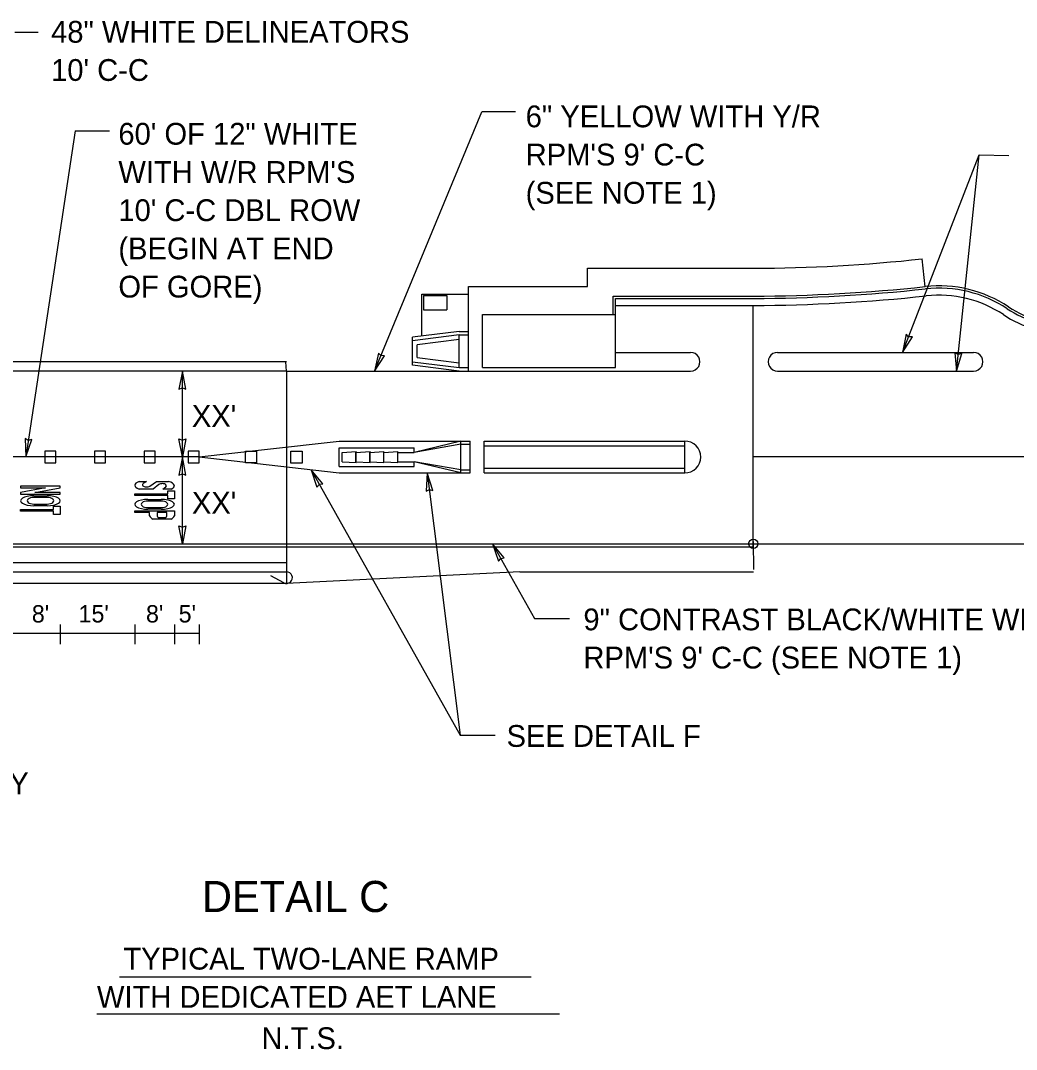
# Model space of a CAD drawing. Extents: x 583689 to 590775, y 1496016 to 1497365.
# Drawn here: x 587578.1 to 587898.1, y 1496113.3 to 1496443.8 of the extents above; entities that cross this region are included whole.
import ezdxf

# ---------------------------------------------------------------- set-up
doc = ezdxf.new("R2010")
doc.units = 0
for name, color, linetype in [('2', 7, 'Continuous'), ('21', 7, 'Continuous'), ('22', 7, 'Continuous'), ('28', 7, 'Continuous'), ('3', 7, 'Continuous'), ('41', 7, 'Continuous'), ('42', 7, 'Continuous'), ('46', 7, 'Continuous'), ('50', 7, 'Continuous'), ('52', 7, 'Continuous'), ('PavtMessage', 7, 'Continuous'), ('TextLabel', 7, 'Continuous')]:
    doc.layers.add(name, color=color, linetype=linetype)

msp = doc.modelspace()

# ---------------------------------------------------------------- linework, layer by layer
at = {"layer": '2'}
for p, q in [((587760.33, 1496364.3), (587813.57, 1496364.31)), ((587760.33, 1496358.37), (587760.33, 1496364.3)), ((587868.77, 1496358.35), (587867.8, 1496367.29)), ((587722.07, 1496349.37), (587722.07, 1496358.37)), ((587722.07, 1496358.37), (587760.33, 1496358.37)), ((587707.07, 1496355.99), (587722.07, 1496356)), ((587707.08, 1496342.5), (587707.07, 1496355.99)), ((587768.57, 1496355.31), (587813.56, 1496355.31)), ((587768.57, 1496349.38), (587768.57, 1496355.3)), ((587769.32, 1496332.37), (587769.32, 1496354.56)), ((587769.32, 1496354.56), (587813.56, 1496354.56)), ((587769.32, 1496352.31), (587813.57, 1496352.31)), ((587813.57, 1496275.75), (587813.57, 1496352.31)), ((587722.07, 1496331.25), (587722.07, 1496349.37)), ((587726.57, 1496349.37), (587769.32, 1496349.38)), ((587726.57, 1496332.38), (587726.57, 1496349.37)), ((587719.07, 1496344), (587704.07, 1496342.13)), ((587719.07, 1496342.87), (587704.07, 1496340.99)), ((587704.07, 1496333.13), (587704.07, 1496342.13)), ((587719.07, 1496341.35), (587705.57, 1496339.67)), ((587719.07, 1496344), (587722.07, 1496344)), ((587719.07, 1496332.38), (587719.07, 1496342.88)), ((587719.07, 1496342.88), (587722.07, 1496342.88)), ((587705.57, 1496335.58), (587705.57, 1496339.67)), ((587705.57, 1496335.58), (587719.07, 1496333.9)), ((587769.32, 1496337.25), (587793.42, 1496337.25)), ((587663.57, 1496331.25), (587326.15, 1496331.25)), ((587663.57, 1496331.25), (587793.42, 1496331.25)), ((587663.58, 1496331.25), (587663.58, 1496275.75)), ((587704.07, 1496334.26), (587719.07, 1496332.38)), ((587719.07, 1496331.25), (587704.07, 1496333.13)), ((587719.07, 1496332.38), (587722.07, 1496332.39)), ((587726.57, 1496332.38), (587769.32, 1496332.37)), ((587656.54, 1496306.03), (587680.53, 1496308.76)), ((587680.53, 1496308.73), (587722.57, 1496308.75)), ((587719.57, 1496308.75), (587704.57, 1496305.13)), ((587719.57, 1496298.5), (587719.57, 1496308.75)), ((587722.57, 1496298.5), (587722.57, 1496308.75)), ((587727.07, 1496298.5), (587727.07, 1496308.75)), ((587727.07, 1496308.75), (587791.54, 1496308.75)), ((587791.54, 1496298.5), (587791.54, 1496308.75)), ((587635.53, 1496303.64), (587656.54, 1496306.03)), ((587680.53, 1496306.63), (587704.57, 1496306.63)), ((587680.53, 1496300.63), (587680.53, 1496306.63)), ((587681.44, 1496305.12), (587685.94, 1496305.37)), ((587681.44, 1496305.12), (587685.94, 1496305.37)), ((587681.44, 1496305.12), (587685.94, 1496305.37)), ((587681.44, 1496305.12), (587685.94, 1496305.37)), ((587681.44, 1496302.12), (587681.44, 1496305.13)), ((587681.44, 1496302.12), (587681.44, 1496305.13)), ((587681.44, 1496302.12), (587681.44, 1496305.13)), ((587681.44, 1496302.12), (587681.44, 1496305.13)), ((587681.44, 1496302.11), (587681.44, 1496305.13)), ((587681.44, 1496302.11), (587681.44, 1496305.13)), ((587681.44, 1496302.11), (587681.44, 1496305.13)), ((587681.44, 1496302.11), (587681.44, 1496305.13)), ((587681.44, 1496302.11), (587681.44, 1496305.13)), ((587681.44, 1496302.11), (587681.44, 1496305.13)), ((587681.44, 1496302.11), (587681.44, 1496305.13)), ((587681.44, 1496302.11), (587681.44, 1496305.13)), ((587681.44, 1496302.1), (587681.44, 1496305.12)), ((587681.44, 1496302.1), (587681.44, 1496305.12)), ((587681.44, 1496302.1), (587681.44, 1496305.12)), ((587681.44, 1496302.1), (587681.44, 1496305.12)), ((587685.9, 1496305.12), (587690.4, 1496305.38)), ((587685.9, 1496305.12), (587690.4, 1496305.38)), ((587685.9, 1496305.12), (587690.4, 1496305.38)), ((587685.9, 1496305.12), (587690.4, 1496305.38)), ((587685.9, 1496302.11), (587685.9, 1496305.12)), ((587685.9, 1496302.11), (587685.9, 1496305.12)), ((587685.9, 1496302.11), (587685.9, 1496305.12)), ((587685.9, 1496302.11), (587685.9, 1496305.12)), ((587685.91, 1496302.1), (587685.9, 1496305.12)), ((587685.91, 1496302.1), (587685.9, 1496305.12)), ((587685.91, 1496302.1), (587685.9, 1496305.12)), ((587685.91, 1496302.1), (587685.9, 1496305.12)), ((587685.91, 1496302.1), (587685.9, 1496305.12)), ((587685.91, 1496302.1), (587685.9, 1496305.12)), ((587685.91, 1496302.1), (587685.9, 1496305.12)), ((587685.91, 1496302.1), (587685.9, 1496305.12)), ((587685.94, 1496301.87), (587685.94, 1496305.37)), ((587685.94, 1496301.87), (587685.94, 1496305.37)), ((587685.94, 1496301.87), (587685.94, 1496305.37)), ((587685.94, 1496301.87), (587685.94, 1496305.37)), ((587690.36, 1496305.13), (587694.86, 1496305.38)), ((587690.36, 1496305.13), (587694.86, 1496305.38)), ((587690.36, 1496302.11), (587690.36, 1496305.13)), ((587690.36, 1496302.11), (587690.36, 1496305.13)), ((587690.36, 1496302.11), (587690.36, 1496305.13)), ((587690.36, 1496302.11), (587690.36, 1496305.13)), ((587690.36, 1496302.11), (587690.36, 1496305.13)), ((587690.36, 1496302.11), (587690.36, 1496305.13)), ((587690.36, 1496302.11), (587690.36, 1496305.13)), ((587690.36, 1496302.11), (587690.36, 1496305.13)), ((587690.4, 1496301.88), (587690.4, 1496305.38)), ((587690.4, 1496301.88), (587690.4, 1496305.38)), ((587690.4, 1496301.88), (587690.4, 1496305.38)), ((587690.4, 1496301.88), (587690.4, 1496305.38)), ((587694.82, 1496305.13), (587699.32, 1496305.38)), ((587694.82, 1496302.11), (587694.82, 1496305.13)), ((587694.82, 1496302.11), (587694.82, 1496305.13)), ((587694.86, 1496301.88), (587694.86, 1496305.38)), ((587694.86, 1496301.88), (587694.86, 1496305.38)), ((587699.32, 1496301.88), (587699.32, 1496305.38)), ((587699.32, 1496305.13), (587704.57, 1496305.13)), ((587719.57, 1496307.76), (587704.57, 1496305.13)), ((587704.57, 1496305.13), (587704.57, 1496306.63)), ((587719.57, 1496307.76), (587722.55, 1496307.76)), ((587727.07, 1496307.25), (587762.14, 1496307.25)), ((587762.14, 1496307.25), (587791.54, 1496307.25)), ((587635.53, 1496303.64), (587539.85, 1496303.64)), ((587635.53, 1496303.64), (587653.24, 1496301.62)), ((587653.24, 1496301.62), (587680.53, 1496298.5)), ((587681.44, 1496302.1), (587685.94, 1496301.87)), ((587681.44, 1496302.1), (587685.94, 1496301.87)), ((587681.44, 1496302.1), (587685.94, 1496301.87)), ((587681.44, 1496302.1), (587685.94, 1496301.87)), ((587685.9, 1496302.11), (587690.4, 1496301.88)), ((587685.9, 1496302.11), (587690.4, 1496301.88)), ((587685.9, 1496302.11), (587690.4, 1496301.88)), ((587685.9, 1496302.11), (587690.4, 1496301.88)), ((587690.36, 1496302.11), (587694.86, 1496301.88)), ((587690.36, 1496302.11), (587694.86, 1496301.88)), ((587694.82, 1496302.11), (587699.32, 1496301.88)), ((587699.32, 1496302.13), (587704.57, 1496302.13)), ((587704.57, 1496300.63), (587704.57, 1496302.19)), ((587719.57, 1496298.5), (587704.57, 1496302.13)), ((587719.57, 1496299.5), (587704.57, 1496302.13)), ((587813.57, 1496303.79), (588039.9, 1496303.8)), ((587680.53, 1496300.63), (587704.57, 1496300.63)), ((587680.53, 1496298.52), (587722.57, 1496298.5)), ((587719.57, 1496299.5), (587722.58, 1496299.5)), ((587727.07, 1496300), (587762.46, 1496300)), ((587727.07, 1496298.5), (587791.54, 1496298.5)), ((587762.46, 1496300), (587791.54, 1496300)), ((587387.69, 1496275.75), (587663.57, 1496275.75)), ((587663.57, 1496275.75), (587774.7, 1496275.75)), ((587663.57, 1496275.75), (588039.9, 1496275.75)), ((587774.7, 1496275.75), (587813.57, 1496275.76)), ((587813.57, 1496274.75), (587813.57, 1496275.75)), ((587813.57, 1496274.75), (587813.57, 1496275.75)), ((587326.15, 1496274.75), (587663.58, 1496274.75)), ((587663.58, 1496274.75), (587813.57, 1496274.75))]:
    msp.add_line(p, q, dxfattribs=at)
for points in [[(587585.91, 1496301.74), (587589.46, 1496301.74), (587589.47, 1496305.54), (587585.91, 1496305.54)], [(587601.86, 1496301.74), (587605.41, 1496301.74), (587605.42, 1496305.54), (587601.86, 1496305.54)], [(587617.81, 1496301.74), (587621.36, 1496301.74), (587621.36, 1496305.54), (587617.81, 1496305.54)], [(587631.98, 1496301.74), (587635.53, 1496301.74), (587635.54, 1496305.54), (587631.98, 1496305.54)], [(587653.97, 1496301.77), (587650.42, 1496301.77), (587650.42, 1496305.56), (587653.98, 1496305.56)], [(587668.55, 1496301.67), (587665, 1496301.67), (587665, 1496305.47), (587668.55, 1496305.47)]]:
    msp.add_lwpolyline(points, close=True, dxfattribs=at)
for centre, radius, start, end in [((587811.34, 1496889.63), 525.38, 270.2388, 276.1694), ((587811.34, 1496889.68), 534.38, 270.2375, 276.1752), ((587811.34, 1496889.68), 535.13, 270.2375, 276.1752), ((587873.18, 1496318.14), 40.5, 56.4357, 96.1704), ((587873.18, 1496318.14), 39.75, 56.4357, 96.1704), ((587811.34, 1496889.68), 537.38, 270.2375, 276.1752), ((587873.18, 1496318.14), 37.5, 56.4357, 96.1704), ((587914.65, 1496380.63), 35.25, 236.4357, 253.0681), ((587914.65, 1496380.63), 34.5, 236.4357, 254.5578), ((587914.65, 1496380.63), 37.5, 236.4357, 269.7206), ((587791.54, 1496303.63), 5.13, 269.9999, 89.9999)]:
    msp.add_arc(centre, radius, start, end, dxfattribs=at)
at = {"layer": '21'}
for p, q in [((587583.82, 1496440.04), (587576.23, 1496440.04)), ((587691.86, 1496331.25), (587726.28, 1496414.56)), ((587737.12, 1496414.56), (587726.28, 1496414.56)), ((587595.7, 1496408.42), (587579.78, 1496303.64)), ((587595.7, 1496408.42), (587606.68, 1496408.42)), ((587861.54, 1496337.25), (587886.12, 1496400.69)), ((587878.81, 1496331.25), (587886.12, 1496400.69)), ((587886.12, 1496400.69), (587895.69, 1496400.51)), ((587630.11, 1496303.64), (587630.11, 1496331.25)), ((587630.11, 1496275.75), (587630.11, 1496303.64)), ((587671.49, 1496299.53), (587719.42, 1496214.25)), ((587708.8, 1496298.51), (587719.42, 1496214.25)), ((587729.78, 1496275.75), (587743.24, 1496251.8)), ((587743.24, 1496251.8), (587754.45, 1496251.8)), ((587590.88, 1496249.83), (587590.88, 1496243.54)), ((587614.8, 1496249.83), (587614.8, 1496243.54)), ((587627.56, 1496249.83), (587627.56, 1496243.54)), ((587635.53, 1496249.83), (587635.53, 1496243.54)), ((587635.53, 1496246.88), (587541.44, 1496246.88)), ((587719.42, 1496214.25), (587730.63, 1496214.25))]:
    msp.add_line(p, q, dxfattribs=at)
at = {"layer": '22'}
for q in [(587663.57, 1496263), (587813.6, 1496266.76)]:
    msp.add_line((587738.57, 1496266.76), q, dxfattribs=at)
at = {"layer": '28'}
msp.add_circle((587813.57, 1496275.76), 1.5, dxfattribs=at)
at = {"layer": '3'}
for p, q in [((587821.35, 1496337.25), (587884.35, 1496337.25)), ((587821.35, 1496331.25), (587884.35, 1496331.25))]:
    msp.add_line(p, q, dxfattribs=at)
for centre, start, end in [((587793.42, 1496334.25), 269.9999, 90.0236), ((587821.35, 1496334.25), 89.9764, 270.0001), ((587884.35, 1496334.25), 269.9999, 90.0236)]:
    msp.add_arc(centre, 3, start, end, dxfattribs=at)
at = {"layer": '41'}
for p, q in [((587326.15, 1496275.75), (587663.57, 1496275.75)), ((587663.57, 1496275.75), (587774.7, 1496275.75)), ((587774.7, 1496275.75), (587813.57, 1496275.75))]:
    msp.add_line(p, q, dxfattribs=at)
at = {"layer": '42'}
for p, q in [((587663.57, 1496334.25), (587326.15, 1496334.25)), ((587663.58, 1496331.25), (587663.38, 1496334.25)), ((587663.57, 1496275.75), (587663.57, 1496263)), ((587813.57, 1496276.51), (587813.6, 1496267.51)), ((587326.15, 1496269.75), (587663.57, 1496269.75)), ((587663.57, 1496263), (587326.15, 1496263))]:
    msp.add_line(p, q, dxfattribs=at)
at = {"layer": '46'}
for p, q in [((587707.63, 1496355.47), (587715.13, 1496355.47)), ((587707.63, 1496355.47), (587707.63, 1496350.97)), ((587715.13, 1496355.47), (587715.13, 1496350.97)), ((587707.63, 1496350.97), (587715.13, 1496350.97)), ((587326.15, 1496266.75), (587663.57, 1496266.75)), ((587662.7, 1496263.22), (587658.49, 1496265.5))]:
    msp.add_line(p, q, dxfattribs=at)
msp.add_arc((587663.57, 1496264.88), 1.88, 242.305, 90.004, dxfattribs=at)
at = {"layer": '50'}
for p, q in [((587609.92, 1496136.68), (587742.15, 1496136.68)), ((587602.66, 1496124.71), (587751.28, 1496124.7))]:
    msp.add_line(p, q, dxfattribs=at)
at = {"layer": '52'}
for p, q in [((587862.63, 1496343.05), (587861.54, 1496337.25)), ((587861.54, 1496337.25), (587864.68, 1496342.25)), ((587863.48, 1496342.25), (587862.63, 1496343.05)), ((587864.68, 1496342.25), (587863.48, 1496342.25)), ((587693.08, 1496337.02), (587691.86, 1496331.25)), ((587691.86, 1496331.25), (587695.11, 1496336.18)), ((587693.91, 1496336.21), (587693.08, 1496337.02)), ((587695.11, 1496336.18), (587693.91, 1496336.21)), ((587879.37, 1496336.58), (587878.34, 1496337.13)), ((587878.34, 1496337.13), (587878.81, 1496331.25)), ((587878.81, 1496331.25), (587880.53, 1496336.9)), ((587880.53, 1496336.9), (587879.37, 1496336.58)), ((587630.11, 1496331.25), (587628.99, 1496325.45)), ((587631.19, 1496325.45), (587630.11, 1496331.25)), ((587628.99, 1496325.45), (587630.11, 1496325.89)), ((587630.11, 1496325.89), (587631.19, 1496325.45)), ((587580.59, 1496308.94), (587579.59, 1496309.54)), ((587579.59, 1496309.54), (587579.78, 1496303.64)), ((587579.78, 1496303.64), (587581.76, 1496309.21)), ((587581.76, 1496309.21), (587580.59, 1496308.94)), ((587630.11, 1496303.64), (587628.99, 1496309.44)), ((587628.99, 1496309.44), (587630.11, 1496309)), ((587630.11, 1496309), (587631.19, 1496309.44)), ((587631.19, 1496309.44), (587630.11, 1496303.64)), ((587630.11, 1496303.64), (587628.99, 1496297.84)), ((587631.19, 1496297.84), (587630.11, 1496303.64)), ((587628.99, 1496297.84), (587630.11, 1496298.28)), ((587630.11, 1496298.28), (587631.19, 1496297.84)), ((587671.49, 1496299.53), (587673.35, 1496293.93)), ((587675.27, 1496295.01), (587671.49, 1496299.53)), ((587708.8, 1496298.51), (587708.42, 1496292.61)), ((587710.6, 1496292.89), (587708.8, 1496298.51)), ((587673.35, 1496293.93), (587674.12, 1496294.86)), ((587674.12, 1496294.86), (587675.27, 1496295.01)), ((587708.42, 1496292.61), (587709.47, 1496293.19)), ((587709.47, 1496293.19), (587710.6, 1496292.89)), ((587630.11, 1496275.75), (587628.99, 1496281.55)), ((587628.99, 1496281.55), (587630.11, 1496281.11)), ((587630.11, 1496281.11), (587631.19, 1496281.55)), ((587631.19, 1496281.55), (587630.11, 1496275.75)), ((587729.78, 1496275.75), (587731.64, 1496270.15)), ((587733.56, 1496271.23), (587729.78, 1496275.75)), ((587731.64, 1496270.15), (587732.4, 1496271.08)), ((587732.4, 1496271.08), (587733.56, 1496271.23))]:
    msp.add_line(p, q, dxfattribs=at)
at = {"layer": 'PavtMessage'}
for p, q in [((587616.24, 1496295.74), (587618.56, 1496295.74)), ((587618.56, 1496295.74), (587617.56, 1496295.08)), ((587619.7, 1496294.29), (587621.75, 1496295.74)), ((587622.55, 1496294.77), (587620.71, 1496293.35)), ((587621.75, 1496295.74), (587625.66, 1496295.74)), ((587590.88, 1496294.22), (587578.12, 1496294.22)), ((587578.12, 1496294.22), (587578.12, 1496293.69)), ((587578.12, 1496293.69), (587586.1, 1496293.69)), ((587586.1, 1496293.69), (587578.12, 1496292.22)), ((587578.12, 1496292.22), (587578.12, 1496291.69)), ((587578.12, 1496291.69), (587590.88, 1496291.69)), ((587582.75, 1496292.22), (587590.88, 1496293.69)), ((587590.88, 1496292.22), (587582.75, 1496292.22)), ((587590.88, 1496293.69), (587590.88, 1496294.22)), ((587590.88, 1496291.69), (587590.88, 1496292.22)), ((587614.8, 1496291.22), (587614.8, 1496291.76)), ((587614.8, 1496291.76), (587625.43, 1496291.76)), ((587620.71, 1496293.35), (587616.24, 1496293.35)), ((587623.85, 1496293.35), (587624.77, 1496294.05)), ((587626.48, 1496293.35), (587623.85, 1496293.35)), ((587625.43, 1496292.82), (587627.56, 1496292.82)), ((587625.43, 1496291.76), (587625.43, 1496292.82)), ((587627.56, 1496292.82), (587627.56, 1496290.16)), ((587582.37, 1496291.16), (587586.63, 1496291.16)), ((587586.63, 1496290.63), (587582.37, 1496290.63)), ((587582.37, 1496288.5), (587586.63, 1496288.5)), ((587625.43, 1496291.22), (587614.8, 1496291.22)), ((587619.05, 1496290.03), (587623.31, 1496290.03)), ((587623.31, 1496289.5), (587619.05, 1496289.5)), ((587625.43, 1496290.16), (587625.43, 1496291.22)), ((587627.56, 1496290.16), (587625.43, 1496290.16)), ((587578.12, 1496286.24), (587578.12, 1496286.77)), ((587578.12, 1496286.77), (587588.75, 1496286.77)), ((587588.75, 1496286.24), (587578.12, 1496286.24)), ((587586.63, 1496287.97), (587582.37, 1496287.97)), ((587588.75, 1496287.83), (587590.88, 1496287.83)), ((587588.75, 1496286.77), (587588.75, 1496287.83)), ((587588.75, 1496285.17), (587588.75, 1496286.24)), ((587590.88, 1496285.17), (587588.75, 1496285.17)), ((587590.88, 1496287.83), (587590.88, 1496285.17)), ((587614.8, 1496286.31), (587627.56, 1496286.31)), ((587614.8, 1496285.77), (587614.8, 1496286.31)), ((587619.59, 1496285.77), (587614.8, 1496285.77)), ((587619.05, 1496287.37), (587623.31, 1496287.37)), ((587623.31, 1496286.84), (587619.05, 1496286.84)), ((587619.59, 1496284.76), (587619.59, 1496285.77)), ((587625.17, 1496285.77), (587621.98, 1496285.77)), ((587621.98, 1496285.77), (587621.98, 1496284.71)), ((587625.17, 1496284.71), (587625.17, 1496285.77)), ((587627.56, 1496286.31), (587627.56, 1496284.76)), ((587626.49, 1496283.65), (587620.65, 1496283.65)), ((587622.38, 1496284.18), (587624.76, 1496284.18))]:
    msp.add_line(p, q, dxfattribs=at)
for centre, major_axis, ratio, start_param, end_param in [((587619.05, 1496294.55), (-4.25, 0), 0.375, 5.435123, 7.131247), ((587618.61, 1496294.68), (1.33, 0), 0.5, 2.490106, 5.666015), ((587623.66, 1496294.41), (1.33, 0), 0.5, 5.699287, 8.851109), ((587623.31, 1496294.41), (4.25, 0), 0.375, 5.553458, 7.268296), ((587582.37, 1496289.57), (4.25, 0), 0.375, 1.570796, 4.712389), ((587582.37, 1496289.57), (2.13, 0), 0.5, 1.570796, 4.712389), ((587586.63, 1496289.57), (4.25, 0), 0.375, 4.712389, 7.853982), ((587586.63, 1496289.57), (2.13, 0), 0.5, 4.712389, 7.853982), ((587619.05, 1496288.43), (4.25, 0), 0.375, 1.570796, 4.712389), ((587619.05, 1496288.43), (2.13, 0), 0.5, 1.570796, 4.712389), ((587623.31, 1496288.43), (4.25, 0), 0.375, 4.712389, 7.853982), ((587623.31, 1496288.43), (2.13, 0), 0.5, 4.712389, 7.853982), ((587623.57, 1496285.77), (4.25, 0), 0.6875, 3.497014, 3.955933), ((587623.57, 1496284.71), (1.59, 0), 0.5, 3.141593, 3.87132), ((587623.57, 1496284.71), (1.59, 0), 0.5, 5.553458, 6.283185), ((587623.57, 1496285.77), (4.25, 0), 0.6875, 5.468845, 5.927764)]:
    msp.add_ellipse(centre, major_axis=major_axis, ratio=ratio, start_param=start_param, end_param=end_param, dxfattribs=at)

# ---------------------------------------------------------------- texts
at = {"layer": '21'}
for s, p in [('48" WHITE DELINEATORS', (587587.93, 1496436.74)), ("10' C-C", (587587.93, 1496424.47)), ('6" YELLOW WITH Y/R ', (587740.42, 1496409.57)), ('60\' OF 12" WHITE', (587609.55, 1496403.98)), ("RPM'S 9' C-C", (587740.42, 1496397.29)), ("WITH W/R RPM'S", (587609.55, 1496391.7)), ('(SEE NOTE 1)', (587740.42, 1496385.01)), ("10' C-C DBL ROW", (587609.55, 1496379.43)), ('(BEGIN AT END', (587609.55, 1496367.15)), ('OF GORE)', (587609.55, 1496354.87)), ('9" CONTRAST BLACK/WHITE WITH W/R', (587758.97, 1496247.96)), ("RPM'S 9' C-C (SEE NOTE 1)", (587758.97, 1496235.69)), ('SEE DETAIL F', (587734.27, 1496210.51)), ('TO BE USED BASED ON RAMP GEOMETRY', (587387.25, 1496195.29))]:
    msp.add_text(s, height=7, dxfattribs=at).set_placement(p)
for p in [(587633.17, 1496313.3), (587633.17, 1496285.41)]:
    msp.add_text("XX'", height=7, rotation=0.2102, dxfattribs=at).set_placement(p)
at = {"layer": '50'}
msp.add_text('DETAIL C', height=10, dxfattribs=at).set_placement((587636.38, 1496157.44))
for s, p in [('TYPICAL TWO-LANE RAMP', (587611.16, 1496138.96)), ('WITH DEDICATED AET LANE', (587602.66, 1496126.68)), ('N.T.S.', (587655.52, 1496113.41))]:
    msp.add_text(s, height=7, rotation=359.9987, dxfattribs=at).set_placement(p)
at = {"layer": 'TextLabel'}
for s, p in [("8'", (587581.74, 1496250.47)), ("15'", (587596.75, 1496250.47)), ("8'", (587618.42, 1496250.47)), ("5'", (587628.92, 1496250.47))]:
    msp.add_text(s, height=5.582, dxfattribs=at).set_placement(p)

doc.saveas('drawing.dxf')
